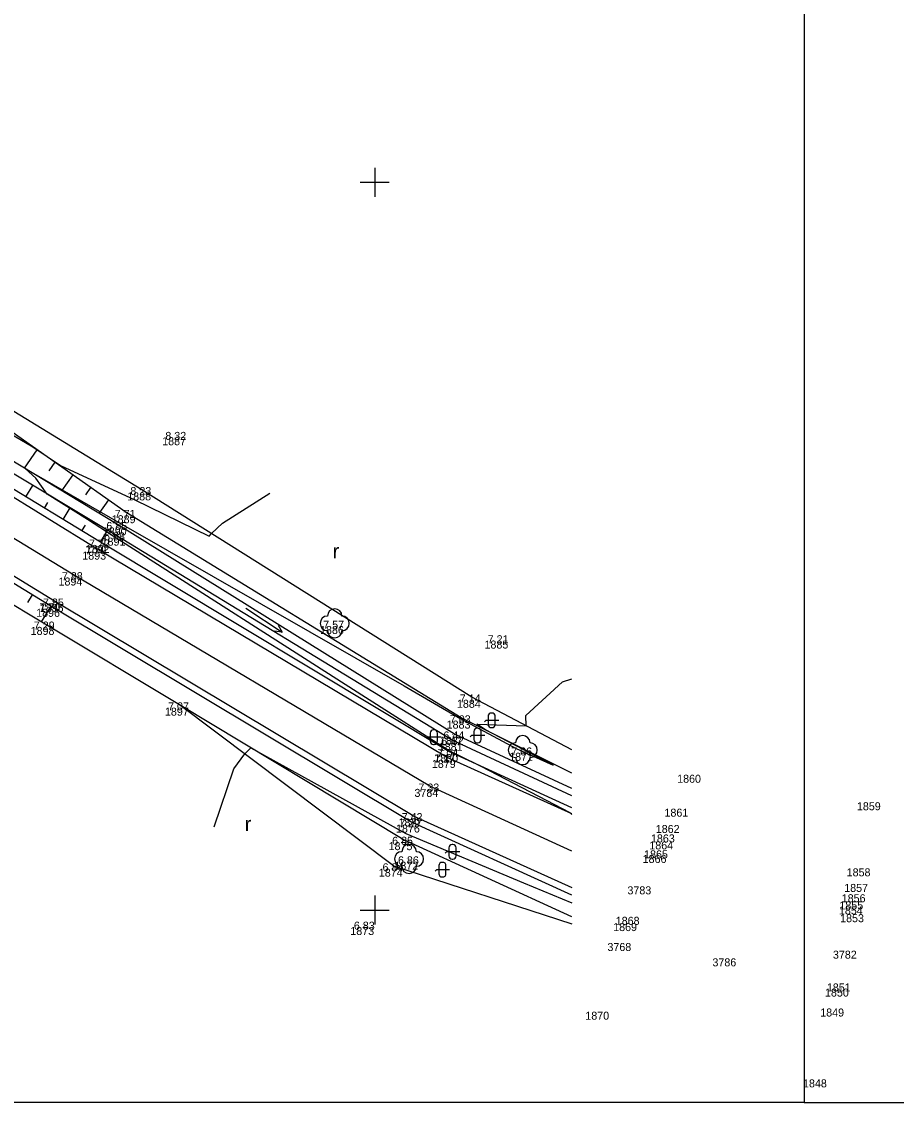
# Model space of a CAD drawing. Extents: x -740053 to -737517, y -1033516 to -1032465.
# Drawn here: x -738224.3 to -738164.2, y -1032613.2 to -1032539 of the extents above; entities that cross this region are included whole.
import ezdxf

# ---------------------------------------------------------------- set-up
doc = ezdxf.new("R2010")
doc.units = 0
for name, color, linetype in [('bod-cislo', 7, 'Continuous'), ('bod-oznac', 7, 'Continuous'), ('bod-vyska', 7, 'Continuous'), ('bod-vyska100', 7, 'Continuous'), ('Contours', 7, 'Continuous'), ('ctv-sit', 7, 'Continuous'), ('dopl-znacky', 7, 'Continuous'), ('osa-komunikace', 7, 'Continuous'), ('Predmety bez rozlišeni', 7, 'Continuous'), ('promika-formát', 7, 'Continuous'), ('rozhraní kultůr', 7, 'Continuous'), ('silnice', 7, 'Continuous'), ('Technické šrafy', 7, 'Continuous'), ('Terenni-hrana', 7, 'Continuous'), ('Znacky-kultury', 7, 'Continuous')]:
    doc.layers.add(name, color=color, linetype=linetype)

# ---------------------------------------------------------------- blocks, each defined once
blk = doc.blocks.new('POINT_DISPLAY')
blk.add_line((0, 0), (0, 0))
blk = doc.blocks.new('p_strom')
for centre, start, end in [((0, 1), 0, 180), ((-1, 0), 90, 270), ((1, 0), 270, 90), ((0, -1), 180, 0)]:
    blk.add_arc(centre, 1, start, end)
at = {"rotation": -180}
blk.add_blockref('POINT_DISPLAY', (0, 0), dxfattribs=at)
blk = doc.blocks.new('vo_votok')
for p, q in [((-3, 0), (3, 0)), ((2, 0.5), (3, 0)), ((3, 0), (2, -0.5))]:
    blk.add_line(p, q)
blk = doc.blocks.new('p_orna')
blk.add_text('r', height=2).set_placement((0, 0))
blk = doc.blocks.new('p_neplod')
for p, q in [((-0.82, 0), (-0.99, -0.18)), ((1, 0), (-0.82, 0)), ((-0.49, 0.56), (-0.49, -0.55)), ((0.05, 1.01), (-0.04, 1.01)), ((0.5, -0.55), (0.5, 0.56)), ((-0.04, -1), (0.05, -1))]:
    blk.add_line(p, q)
for centre, start, end in [((-0.04, 0.56), 90, 180), ((0.05, 0.56), 0, 90), ((-0.04, -0.55), 180, 270), ((0.05, -0.55), 270, 0)]:
    blk.add_arc(centre, 0.45, start, end)
blk = doc.blocks.new('ctvsit')
for p, q in [((0, -2), (0, 2)), ((2, 0), (-2, 0))]:
    blk.add_line(p, q)

msp = doc.modelspace()

# ---------------------------------------------------------------- linework, layer by layer
at = {"layer": 'Contours'}
for points in [[(-738241.595, -1032557.53), (-738223.493, -1032568.169), (-738221.595, -1032569.446), (-738216.478, -1032571.814), (-738211.383, -1032574.319), (-738211.216, -1032574.127), (-738210.464, -1032573.415), (-738207.214, -1032571.357)], [(-738186.454, -1032593.426), (-738186.58, -1032593.328), (-738188.716, -1032592.207), (-738192.682, -1032590.125), (-738194.17, -1032589.406), (-738194.884, -1032589.055), (-738200.635, -1032585.39), (-738217.984, -1032574.301), (-738219.736, -1032573.163), (-738222.501, -1032571.429), (-738223.281, -1032570.334), (-738224.027, -1032569.672), (-738217.575, -1032573.375), (-738197.988, -1032584.587), (-738194.074, -1032586.856), (-738190.284, -1032588.904), (-738189.12, -1032589.416), (-738187.73, -1032590.036), (-738192.392, -1032587.627), (-738192.986, -1032587.232), (-738189.587, -1032587.346), (-738189.616, -1032586.635), (-738187.106, -1032584.325), (-738186.454, -1032584.112)], [(-738211.04, -1032594.292), (-738209.694, -1032590.305), (-738208.933, -1032589.276), (-738208.52, -1032588.85), (-738197.866, -1032594.738), (-738189.779, -1032598.129), (-738186.454, -1032599.5)]]:
    msp.add_lwpolyline(points, dxfattribs=at)
at = {"layer": 'osa-komunikace'}
for p, q in [((-738220.71, -1032576.97), (-738243.97, -1032562.76)), ((-738196.21, -1032591.491), (-738220.71, -1032576.97)), ((-738186.454, -1032595.957), (-738196.21, -1032591.491))]:
    msp.add_line(p, q, dxfattribs=at)
at = {"layer": 'Predmety bez rozlišeni'}
msp.add_line((-738170.499, -1032613.213), (-738275.499, -1032613.213), dxfattribs=at)
at = {"layer": 'promika-formát'}
msp.add_lwpolyline([(-738170.499, -1032613.213), (-738065.499, -1032613.213), (-738065.499, -1032464.713), (-738170.499, -1032464.713)], close=True, dxfattribs=at)
at = {"layer": 'rozhraní kultůr'}
for p, q in [((-738216, -1032571.12), (-738240.74, -1032556.01)), ((-738193.33, -1032585.37), (-738216, -1032571.12)), ((-738186.454, -1032589), (-738193.33, -1032585.37))]:
    msp.add_line(p, q, dxfattribs=at)
at = {"layer": 'silnice'}
for p, q in [((-738219.09, -1032575.19), (-738242.76, -1032560.55)), ((-738222.01, -1032578.78), (-738245.14, -1032564.64)), ((-738195.08, -1032589.5), (-738219.09, -1032575.19)), ((-738197.36, -1032593.52), (-738222.01, -1032578.78)), ((-738186.454, -1032593.385), (-738195.08, -1032589.5)), ((-738197.36, -1032593.52), (-738186.454, -1032598.458))]:
    msp.add_line(p, q, dxfattribs=at)
at = {"layer": 'Technické šrafy'}
for p, q in [((-738223.21, -1032568.369), (-738224.098, -1032569.628)), ((-738221.984, -1032569.233), (-738222.398, -1032569.82)), ((-738220.758, -1032570.097), (-738221.527, -1032571.188)), ((-738223.977, -1032571.614), (-738223.5, -1032570.829)), ((-738219.532, -1032570.961), (-738219.886, -1032571.464)), ((-738222.695, -1032572.393), (-738222.455, -1032571.997)), ((-738218.306, -1032571.826), (-738218.955, -1032572.747)), ((-738221.414, -1032573.172), (-738220.929, -1032572.374)), ((-738220.132, -1032573.951), (-738219.887, -1032573.549)), ((-738218.85, -1032574.73), (-738218.357, -1032573.919)), ((-738223.539, -1032578.336), (-738223.871, -1032578.878)), ((-738222.26, -1032579.12), (-738222.917, -1032580.193))]:
    msp.add_line(p, q, dxfattribs=at)
at = {"layer": 'Terenni-hrana'}
for p, q in [((-738217.08, -1032572.69), (-738240.74, -1032556.01)), ((-738217.68, -1032573.52), (-738242.22, -1032558.64)), ((-738217.84, -1032574.23), (-738242.7, -1032559.29)), ((-738218.85, -1032574.73), (-738242.64, -1032560.27)), ((-738222.26, -1032579.12), (-738245.42, -1032564.93)), ((-738222.64, -1032580.36), (-738246.26, -1032566.14)), ((-738194.05, -1032586.8), (-738217.08, -1032572.69)), ((-738194.52, -1032587.91), (-738217.68, -1032573.52)), ((-738194.67, -1032588.32), (-738217.84, -1032574.23)), ((-738194.9, -1032589.11), (-738218.85, -1032574.73)), ((-738197.53, -1032593.94), (-738222.26, -1032579.12)), ((-738213.41, -1032585.91), (-738222.64, -1032580.36)), ((-738198.7, -1032596.97), (-738213.41, -1032585.91)), ((-738198.04, -1032595.15), (-738213.41, -1032585.91)), ((-738186.454, -1032590.59), (-738194.05, -1032586.8)), ((-738186.454, -1032592.146), (-738194.67, -1032588.32)), ((-738186.454, -1032591.64), (-738194.52, -1032587.91)), ((-738186.454, -1032592.976), (-738194.9, -1032589.11)), ((-738186.454, -1032598.969), (-738197.53, -1032593.94)), ((-738186.454, -1032600.475), (-738198.04, -1032595.15)), ((-738198.7, -1032596.97), (-738186.454, -1032600.946))]:
    msp.add_line(p, q, dxfattribs=at)

# ---------------------------------------------------------------- block references
at = {"layer": 'bod-oznac'}
for p in [(-738213.6, -1032567.33), (-738216, -1032571.12), (-738217.08, -1032572.69), (-738217.68, -1032573.52), (-738217.84, -1032574.23), (-738218.85, -1032574.73), (-738219.09, -1032575.19), (-738220.71, -1032576.97), (-738222.26, -1032579.12), (-738222.01, -1032578.78), (-738222.64, -1032580.36), (-738202.75, -1032580.3), (-738191.45, -1032581.3), (-738193.33, -1032585.37), (-738213.41, -1032585.91), (-738194.05, -1032586.8), (-738194.67, -1032588.32), (-738194.52, -1032587.91), (-738194.9, -1032589.11), (-738189.83, -1032589.01), (-738195.08, -1032589.5), (-738196.21, -1032591.491), (-738197.36, -1032593.52), (-738197.53, -1032593.94), (-738198.04, -1032595.15), (-738197.64, -1032596.49), (-738198.7, -1032596.97), (-738200.67, -1032600.98)]:
    msp.add_blockref('POINT_DISPLAY', p, dxfattribs=at)
at = {"layer": 'ctv-sit', "xscale": 0.5, "yscale": 0.5, "rotation": 180}
for p in [(-738200, -1032550), (-738200, -1032600)]:
    msp.add_blockref('ctvsit', p, dxfattribs=at)
at = {"layer": 'dopl-znacky', "xscale": 0.5, "yscale": 0.5, "rotation": -33.275376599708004}
msp.add_blockref('vo_votok', (-738207.615, -1032580.084), dxfattribs=at)
at = {"layer": 'Znacky-kultury', "xscale": 0.5, "yscale": 0.5}
for name, p in [('p_orna', (-738202.885, -1032575.837)), ('p_strom', (-738202.75, -1032580.3)), ('p_neplod', (-738191.967, -1032586.968)), ('p_neplod', (-738195.938, -1032588.123)), ('p_neplod', (-738192.944, -1032588.007)), ('p_strom', (-738189.83, -1032589.01)), ('p_orna', (-738208.929, -1032594.579)), ('p_strom', (-738197.64, -1032596.49)), ('p_neplod', (-738194.656, -1032595.998)), ('p_neplod', (-738195.354, -1032597.227))]:
    msp.add_blockref(name, p, dxfattribs=at)

# ---------------------------------------------------------------- texts
at = {"layer": 'bod-cislo'}
for s, p in [('1887', (-738214.608, -1032568.063)), ('1888', (-738217.008, -1032571.853)), ('1889', (-738218.075, -1032573.423)), ('1890', (-738218.688, -1032574.253)), ('1892', (-738219.858, -1032575.463)), ('1891', (-738218.77, -1032574.963)), ('1893', (-738220.098, -1032575.923)), ('1894', (-738221.731, -1032577.703)), ('1896', (-738223.268, -1032579.853)), ('1895', (-738223.018, -1032579.513)), ('1898', (-738223.648, -1032581.093)), ('1886', (-738203.758, -1032581.033)), ('1885', (-738192.458, -1032582.033)), ('1897', (-738214.418, -1032586.643)), ('1884', (-738194.351, -1032586.103)), ('1883', (-738195.058, -1032587.533)), ('1882', (-738195.528, -1032588.643)), ('1881', (-738195.6, -1032589.053)), ('1879', (-738196.075, -1032590.233)), ('1880', (-738195.908, -1032589.843)), ('1871', (-738190.76, -1032589.743)), ('1860', (-738179.218, -1032591.253)), ('3784', (-738197.271, -1032592.224)), ('1859', (-738166.865, -1032593.143)), ('1861', (-738180.09, -1032593.583)), ('1876', (-738198.538, -1032594.673)), ('1877', (-738198.368, -1032594.253)), ('1862', (-738180.688, -1032594.703)), ('1863', (-738181.018, -1032595.353)), ('1875', (-738199.048, -1032595.883)), ('1864', (-738181.131, -1032595.833)), ('1866', (-738181.588, -1032596.763)), ('1865', (-738181.488, -1032596.443)), ('1874', (-738199.721, -1032597.703)), ('1872', (-738198.648, -1032597.223)), ('1858', (-738167.568, -1032597.683)), ('3783', (-738182.634, -1032598.919)), ('1857', (-738167.738, -1032598.753)), ('1855', (-738168.068, -1032599.953)), ('1856', (-738167.908, -1032599.463)), ('1854', (-738168.101, -1032600.303)), ('1853', (-738168.018, -1032600.833)), ('1869', (-738183.615, -1032601.443)), ('1868', (-738183.438, -1032601.013)), ('1873', (-738201.678, -1032601.713)), ('3768', (-738184.008, -1032602.813)), ('3782', (-738168.513, -1032603.34)), ('3786', (-738176.793, -1032603.867)), ('1850', (-738169.058, -1032605.943)), ('1851', (-738168.93, -1032605.593)), ('1849', (-738169.385, -1032607.313)), ('1870', (-738185.528, -1032607.533)), ('1848', (-738170.568, -1032612.183))]:
    msp.add_text(s, height=0.55, dxfattribs=at).set_placement(p)
at = {"layer": 'bod-vyska'}
for s, p in [('8 32', (-738214.389, -1032567.697)), ('8 23', (-738216.789, -1032571.487)), ('7 71', (-738217.869, -1032573.057)), ('6 85', (-738218.443, -1032573.887)), ('6 88', (-738218.603, -1032574.597)), ('7 79', (-738219.879, -1032575.557)), ('7 72', (-738219.639, -1032575.097)), ('7 88', (-738221.499, -1032577.337)), ('7 85', (-738222.799, -1032579.147)), ('7 70', (-738223.049, -1032579.487)), ('7 29', (-738223.429, -1032580.727)), ('7 57', (-738203.539, -1032580.667)), ('7 21', (-738192.239, -1032581.667)), ('7 14', (-738194.158, -1032585.737)), ('7 07', (-738214.199, -1032586.277)), ('7 03', (-738194.839, -1032587.167)), ('6 47', (-738195.433, -1032588.687)), ('6 44', (-738195.283, -1032588.277)), ('7 04', (-738195.689, -1032589.477)), ('7 06', (-738190.619, -1032589.377)), ('7 17', (-738195.908, -1032589.867)), ('7 33', (-738196.999, -1032591.858)), ('7 42', (-738198.149, -1032593.887)), ('7 29', (-738198.319, -1032594.307)), ('6 85', (-738198.803, -1032595.517)), ('6 86', (-738198.403, -1032596.857)), ('6 84', (-738199.463, -1032597.337)), ('6 83', (-738201.433, -1032601.347))]:
    msp.add_text(s, height=0.55, dxfattribs=at).set_placement(p)
at = {"layer": 'bod-vyska100'}
for s, p in [('258 32', (-738213.767, -1032567.363)), ('258 23', (-738216.167, -1032571.153)), ('257 71', (-738217.247, -1032572.723)), ('256 85', (-738217.847, -1032573.553)), ('256 88', (-738218.007, -1032574.263)), ('257 72', (-738219.017, -1032574.763)), ('257 79', (-738219.257, -1032575.223)), ('257 88', (-738220.877, -1032577.003)), ('257 70', (-738222.427, -1032579.153)), ('257 85', (-738222.177, -1032578.813)), ('257 29', (-738222.807, -1032580.393)), ('257 57', (-738202.917, -1032580.333)), ('257 21', (-738191.617, -1032581.333)), ('257 14', (-738193.501, -1032585.403)), ('257 07', (-738213.577, -1032585.943)), ('257 03', (-738194.217, -1032586.833)), ('256 47', (-738194.837, -1032588.353)), ('256 44', (-738194.687, -1032587.943)), ('257 04', (-738195.067, -1032589.143)), ('257 06', (-738189.997, -1032589.043)), ('257 17', (-738195.251, -1032589.533)), ('257 33', (-738196.377, -1032591.524)), ('257 42', (-738197.527, -1032593.553)), ('257 29', (-738197.697, -1032593.973)), ('256 85', (-738198.207, -1032595.183)), ('256 86', (-738197.807, -1032596.523)), ('256 84', (-738198.867, -1032597.003)), ('256 83', (-738200.837, -1032601.013))]:
    msp.add_text(s, height=0.05, dxfattribs=at).set_placement(p)

doc.saveas('drawing.dxf')
